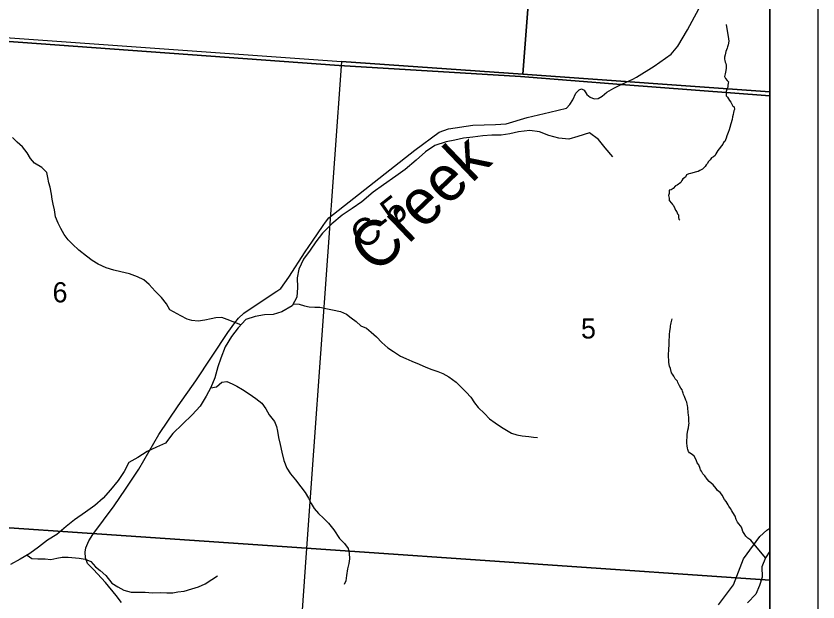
# Model space of a CAD drawing. Extents: x 0 to 34, y 0 to 22.
# Drawn here: x 7.329 to 9, y 19.223 to 20.443 of the extents above; entities that cross this region are included whole.
import ezdxf

# ---------------------------------------------------------------- set-up
doc = ezdxf.new("R2010")
doc.units = 0
for name, color, linetype in [('GM_X_Corporation', 7, 'Continuous'), ('GM_X_County_Road', 7, 'Continuous'), ('GM_X_County_Road_Text', 7, 'Continuous'), ('GM_X_Minor_River', 7, 'Continuous'), ('GM_X_Minor_River_Text', 7, 'Continuous'), ('GM_X_Section_Text', 7, 'Continuous'), ('SH_Data', 7, 'Continuous')]:
    doc.layers.add(name, color=color, linetype=linetype)

msp = doc.modelspace()

# ---------------------------------------------------------------- linework, layer by layer
at = {"layer": 'GM_X_Corporation'}
for points in [[(3.3441, 14.1), (8.9, 14.1), (8.9, 20.9), (2.1, 20.9), (2.1, 16.1353), (2.1457, 16.065), (2.3447, 15.6926), (2.4297, 15.5215), (2.465, 15.4504), (2.4884, 15.4033), (2.5769, 15.2135), (2.7849, 14.8403), (2.8931, 14.6544), (3.0297, 14.4867), (3.1386, 14.3654), (3.228, 14.2415)], [(8.9, 20.2763), (8.9, 20.9), (6.9348, 20.9), (6.9032, 20.4198), (8.0028, 20.34), (8.3805, 20.3169), (8.59, 20.3005)], [(8.4295, 20.9), (6.9414, 20.9), (6.9084, 20.4264), (8.0074, 20.3484), (8.3851, 20.3217)], [(8.9, 20.285), (8.9, 20.9), (8.4295, 20.9), (8.3851, 20.3217)], [(8.9, 16.2015), (8.9, 20.2763), (8.59, 20.3005), (8.3805, 20.3169), (8.0028, 20.34), (6.9032, 20.4198), (6.8961, 20.3303), (6.835, 19.4037), (6.824, 19.3005), (6.7876, 18.7583), (6.7629, 18.3924), (6.7536, 18.2991), (6.7043, 17.4985), (6.6962, 17.3669), (6.6852, 17.2401), (6.6249, 16.3344), (7.5782, 16.28), (7.7162, 16.2721), (7.873, 16.2628)], [(6.9084, 20.4264), (8.0074, 20.3484), (7.9347, 19.3346), (6.8376, 19.4096), (6.9011, 20.3385)], [(8.9, 19.2681), (8.9, 20.285), (8.3851, 20.3217), (8.0074, 20.3484), (7.9347, 19.3346)], [(7.9347, 19.3346), (7.864, 18.3242), (6.7676, 18.3985), (6.8303, 19.3047), (6.8376, 19.4096)], [(8.9, 18.2556), (8.9, 19.2681), (7.9347, 19.3346), (7.864, 18.3242)]]:
    msp.add_lwpolyline(points, close=True, dxfattribs=at)
at = {"layer": 'GM_X_County_Road'}
for points in [[(8.6142, 20.3116), (8.6222, 20.3154), (8.6587, 20.3383), (8.6939, 20.3635), (8.7082, 20.3797), (8.7282, 20.4138), (8.7614, 20.4759), (8.774, 20.4915)], [(7.9744, 20.0134), (7.9812, 20.0225), (8.1602, 20.1635), (8.2106, 20.2007), (8.2302, 20.2076), (8.2812, 20.2158), (8.3284, 20.2166), (8.3502, 20.2185), (8.394, 20.2311), (8.4412, 20.2427), (8.4762, 20.2506), (8.4834, 20.2588), (8.4895, 20.2685), (8.4959, 20.2823), (8.5023, 20.2893), (8.5076, 20.291), (8.513, 20.2883), (8.5187, 20.2793), (8.5257, 20.2736), (8.5338, 20.2702), (8.5418, 20.2712), (8.5505, 20.2759), (8.5602, 20.2839), (8.575, 20.2927), (8.5902, 20.3), (8.6142, 20.3116)], [(7.549, 19.2211), (7.5381, 19.2359), (7.5159, 19.2631), (7.4908, 19.2899), (7.4785, 19.3026), (7.4742, 19.3142), (7.4735, 19.3262), (7.475, 19.3351), (7.4813, 19.3499), (7.4897, 19.3633), (7.5338, 19.4229), (7.5572, 19.4574), (7.5856, 19.4991), (7.6269, 19.5712), (7.6673, 19.6308), (7.7042, 19.6828), (7.7708, 19.7836), (7.785, 19.8041), (7.7931, 19.8133), (7.8041, 19.8243), (7.8441, 19.8513), (7.8729, 19.8698), (7.8811, 19.8753), (7.8976, 19.8992), (7.9316, 19.9515), (7.9473, 19.9737), (7.9695, 20.0068), (7.9744, 20.0134)], [(8.7925, 19.2167), (8.824, 19.2581), (8.8449, 19.3126), (8.879, 19.3592), (8.8938, 19.3721), (8.9, 19.3763)]]:
    msp.add_lwpolyline(points, dxfattribs=at)
at = {"layer": 'GM_X_Minor_River'}
for points in [[(8.8087, 20.4253), (8.8133, 20.3951), (8.814, 20.3905), (8.8127, 20.3825), (8.8119, 20.3784), (8.8111, 20.3757), (8.8095, 20.3723), (8.8083, 20.3686), (8.8067, 20.3621), (8.8051, 20.3572), (8.8054, 20.3527), (8.8061, 20.35), (8.8064, 20.3469), (8.8079, 20.3439), (8.8086, 20.3404), (8.8085, 20.3332), (8.8072, 20.3257), (8.8064, 20.3222), (8.8055, 20.3166), (8.8073, 20.3127), (8.8111, 20.3085), (8.8133, 20.3058), (8.8132, 20.3028), (8.812, 20.2978), (8.812, 20.2948), (8.8104, 20.2907), (8.8091, 20.2857), (8.8087, 20.2827), (8.8086, 20.2766), (8.8116, 20.2739), (8.8134, 20.2705), (8.816, 20.2666), (8.8182, 20.2636), (8.823, 20.2547), (8.8256, 20.2539), (8.8259, 20.2479), (8.8247, 20.2452), (8.8239, 20.2418), (8.8231, 20.238), (8.8218, 20.2327), (8.821, 20.227), (8.8186, 20.218), (8.8165, 20.2108), (8.8149, 20.2055), (8.8126, 20.2002), (8.8114, 20.1968), (8.8102, 20.1934), (8.8089, 20.1885), (8.8058, 20.1817), (8.8035, 20.1791), (8.8019, 20.1761), (8.7992, 20.1723), (8.7945, 20.1663), (8.7914, 20.1626), (8.7891, 20.1592), (8.7872, 20.1558), (8.786, 20.1521), (8.7821, 20.1498), (8.7779, 20.1476), (8.7752, 20.1435), (8.7717, 20.1398), (8.7694, 20.1352), (8.7671, 20.1326), (8.7647, 20.1296), (8.7593, 20.1236), (8.754, 20.1214), (8.7505, 20.1192), (8.7467, 20.1181), (8.7346, 20.1149), (8.7311, 20.1142), (8.7262, 20.112), (8.7242, 20.1071), (8.7184, 20.1034), (8.7165, 20.1), (8.7141, 20.0959), (8.7068, 20.0903), (8.703, 20.0893), (8.6984, 20.0833), (8.6942, 20.081), (8.69, 20.08), (8.6899, 20.0731), (8.6887, 20.069), (8.6897, 20.0633), (8.69, 20.0587), (8.6952, 20.0533), (8.6967, 20.0506), (8.6993, 20.0479), (8.7018, 20.0418), (8.7029, 20.0387)], [(8.5724, 20.1498), (8.5566, 20.1681), (8.543, 20.1855), (8.5241, 20.1993), (8.4999, 20.1917), (8.481, 20.1865), (8.4605, 20.1881), (8.4393, 20.1942), (8.4197, 20.2018), (8.4, 20.2042), (8.3765, 20.2019), (8.3584, 20.1974), (8.3402, 20.1945), (8.3205, 20.1945), (8.3016, 20.1931), (8.2811, 20.1908), (8.2614, 20.1886), (8.2433, 20.1841), (8.2258, 20.1811), (8.2016, 20.1729), (8.1826, 20.16), (8.1629, 20.1426), (8.1401, 20.123), (8.1204, 20.1094), (8.0946, 20.0913), (8.0734, 20.0762), (8.0498, 20.0557), (8.0294, 20.0422), (8.0089, 20.0278), (7.9876, 20.0097), (7.9679, 19.9908), (7.9542, 19.9726), (7.942, 19.9552), (7.9284, 19.9363), (7.9185, 19.9158), (7.9154, 19.8976), (7.9161, 19.8771), (7.9145, 19.8574), (7.9046, 19.8392), (7.8834, 19.8264), (7.8652, 19.8212), (7.847, 19.8205), (7.8273, 19.8167), (7.8084, 19.8107), (7.7924, 19.7933), (7.778, 19.7751), (7.765, 19.7539), (7.7559, 19.7305), (7.7498, 19.7123), (7.7436, 19.6895), (7.7353, 19.6691), (7.7254, 19.6509), (7.7132, 19.6305), (7.6965, 19.6123), (7.676, 19.5926), (7.6562, 19.5737), (7.641, 19.5533), (7.6221, 19.545), (7.6024, 19.536), (7.5834, 19.5231), (7.5644, 19.5133), (7.5545, 19.4944), (7.5424, 19.4755), (7.5264, 19.4558), (7.5112, 19.4384), (7.4938, 19.4233), (7.474, 19.4097), (7.4513, 19.3938), (7.4338, 19.3795), (7.4141, 19.3628), (7.3951, 19.3515), (7.3762, 19.3364), (7.358, 19.3235), (7.3382, 19.3115), (7.3178, 19.3009)], [(7.798, 19.7994), (7.7817, 19.8061), (7.7693, 19.811), (7.7583, 19.8148), (7.7458, 19.814), (7.736, 19.8125), (7.7227, 19.8091), (7.7087, 19.8072), (7.6955, 19.8087), (7.6856, 19.8114), (7.6731, 19.8182), (7.65, 19.8311), (7.6429, 19.8436), (7.6323, 19.8565), (7.619, 19.8698), (7.6065, 19.8838), (7.5956, 19.8932), (7.5823, 19.8997), (7.5657, 19.9058), (7.5479, 19.9099), (7.5331, 19.9137), (7.5172, 19.9186), (7.5006, 19.9258), (7.4881, 19.9334), (7.476, 19.9429), (7.4605, 19.9554), (7.4469, 19.9675), (7.4378, 19.977), (7.4294, 19.988), (7.4226, 20.0005), (7.417, 20.0115), (7.412, 20.0247), (7.4094, 20.0395), (7.4068, 20.0509), (7.4049, 20.0611), (7.403, 20.0721), (7.4003, 20.0861), (7.3977, 20.0956), (7.3958, 20.1062), (7.3939, 20.1172), (7.3829, 20.1274), (7.3682, 20.1365), (7.3595, 20.1464), (7.3523, 20.1581), (7.3428, 20.1706), (7.3315, 20.1801), (7.3224, 20.1896)], [(8.7029, 20.0387), (8.7059, 20.0353), (8.7073, 20.0311), (8.7092, 20.0284), (8.7098, 20.023), (8.7102, 20.02), (8.712, 20.0173)], [(7.9069, 19.8436), (7.9195, 19.8428), (7.9301, 19.839), (7.9403, 19.8375), (7.9521, 19.8364), (7.9623, 19.8364), (7.9782, 19.8333), (7.9884, 19.8311), (8.0054, 19.8277), (8.0179, 19.822), (8.0278, 19.814), (8.038, 19.8064), (8.0478, 19.7977), (8.0592, 19.7924), (8.069, 19.7841), (8.0804, 19.775), (8.0917, 19.7632), (8.1042, 19.7519), (8.1155, 19.7439), (8.1303, 19.7341), (8.1416, 19.7295), (8.1541, 19.7242), (8.1693, 19.7181), (8.1833, 19.7117), (8.1958, 19.7068), (8.2083, 19.7022), (8.2188, 19.6981), (8.2313, 19.6912), (8.2461, 19.6802), (8.2571, 19.6689), (8.2673, 19.6594), (8.2771, 19.6488), (8.2847, 19.637), (8.2922, 19.6276), (8.3051, 19.6147), (8.3157, 19.6037), (8.3274, 19.5954), (8.3407, 19.5867), (8.3509, 19.5802), (8.3619, 19.5741), (8.3728, 19.5704), (8.3838, 19.5688), (8.3974, 19.5669), (8.4073, 19.5654), (8.416, 19.5647)], [(8.8906, 19.3147), (8.8605, 19.3512), (8.8541, 19.3551), (8.8497, 19.3597), (8.8464, 19.3651), (8.8438, 19.3693), (8.8423, 19.3743), (8.8409, 19.3781), (8.8387, 19.3808), (8.8353, 19.385), (8.8324, 19.3885), (8.8298, 19.3946), (8.8273, 19.4015), (8.8225, 19.4088), (8.8207, 19.4123), (8.8181, 19.4172), (8.814, 19.4223), (8.8126, 19.4249), (8.8089, 19.4318), (8.8052, 19.4361), (8.8026, 19.4411), (8.8012, 19.4445), (8.796, 19.4507), (8.7907, 19.4549), (8.7878, 19.4588), (8.7815, 19.4665), (8.7733, 19.4731), (8.7692, 19.4785), (8.7644, 19.485), (8.7599, 19.4893), (8.7573, 19.4946), (8.7555, 19.4977), (8.7544, 19.5008), (8.7515, 19.508), (8.7486, 19.5126), (8.746, 19.5184), (8.742, 19.526), (8.7379, 19.5295), (8.7323, 19.533), (8.73, 19.5361), (8.729, 19.5403), (8.7283, 19.543), (8.7272, 19.5479), (8.7266, 19.5533), (8.7267, 19.559), (8.7272, 19.5654), (8.7276, 19.5711), (8.7289, 19.5806), (8.7302, 19.5851), (8.731, 19.5912), (8.7315, 19.5946), (8.7311, 19.598), (8.7312, 19.6011), (8.7309, 19.6071), (8.7302, 19.6113), (8.7296, 19.617), (8.7296, 19.6201), (8.7289, 19.6243), (8.7286, 19.6273), (8.7279, 19.6319), (8.7276, 19.6345), (8.7266, 19.6387), (8.7247, 19.6426), (8.7222, 19.6506), (8.72, 19.6544), (8.7189, 19.6571), (8.7179, 19.6613), (8.7168, 19.664), (8.7146, 19.6678), (8.7116, 19.6724), (8.7079, 19.6793), (8.7073, 19.6827), (8.7028, 19.687), (8.6999, 19.6928), (8.6969, 19.6966), (8.6951, 19.7), (8.6926, 19.7084), (8.6904, 19.7138), (8.6894, 19.721), (8.6891, 19.7256), (8.6888, 19.7336), (8.6889, 19.7397), (8.6894, 19.7453), (8.6895, 19.751), (8.69, 19.7556), (8.6902, 19.7689), (8.6907, 19.7731), (8.6908, 19.7799), (8.6916, 19.786), (8.6921, 19.7905), (8.6925, 19.7943), (8.693, 19.7977), (8.6934, 19.8004)], [(8.6934, 19.8004), (8.6942, 19.8038), (8.6955, 19.8091), (8.6966, 19.8119)], [(7.735, 19.6687), (7.7469, 19.6708), (7.7582, 19.6803), (7.7685, 19.6814), (7.7794, 19.6769), (7.7897, 19.672), (7.8014, 19.6651), (7.815, 19.6557), (7.829, 19.6466), (7.8415, 19.6367), (7.8498, 19.625), (7.857, 19.6125), (7.8676, 19.5984), (7.8721, 19.5878), (7.874, 19.578), (7.8763, 19.5651), (7.8797, 19.5507), (7.8835, 19.5348), (7.8876, 19.517), (7.8933, 19.5014), (7.9009, 19.4893), (7.9115, 19.4768), (7.9224, 19.462), (7.9319, 19.4507), (7.9387, 19.4385), (7.944, 19.4275), (7.9504, 19.4173), (7.9595, 19.4067), (7.9697, 19.3969), (7.9807, 19.3866), (7.9913, 19.3726), (8.003, 19.3548), (8.0136, 19.3446), (8.0212, 19.3339), (8.0235, 19.3245), (8.0238, 19.3127), (8.0227, 19.3029), (8.02, 19.2915), (8.0178, 19.2775), (8.0162, 19.2665), (8.0128, 19.2589)], [(8.9, 19.3283), (8.8908, 19.3145), (8.8831, 19.2956), (8.8838, 19.2743), (8.8785, 19.2569), (8.8709, 19.2387), (8.8534, 19.2205)], [(7.3523, 19.3201), (7.3623, 19.3132), (7.3748, 19.3124), (7.3903, 19.3121), (7.402, 19.3109), (7.4141, 19.314), (7.4258, 19.3158), (7.438, 19.3158), (7.4607, 19.3136), (7.4735, 19.312), (7.4856, 19.3067), (7.4947, 19.2958), (7.5046, 19.2882), (7.5163, 19.2776), (7.5292, 19.262), (7.5416, 19.2541), (7.5538, 19.2469), (7.5693, 19.2431), (7.5984, 19.2431), (7.6135, 19.2415), (7.6302, 19.2423), (7.6434, 19.2415), (7.6563, 19.2419), (7.6665, 19.2434), (7.6794, 19.2449), (7.6957, 19.2502), (7.7093, 19.254), (7.7233, 19.2605), (7.7373, 19.2692), (7.7494, 19.2771)]]:
    msp.add_lwpolyline(points, dxfattribs=at)
at = {"layer": 'SH_Data'}
for p, q in [((9, 21), (9, 14)), ((8.9, 20.9), (8.9, 14.1))]:
    msp.add_line(p, q, dxfattribs=at)

# ---------------------------------------------------------------- texts
at = {"layer": 'GM_X_County_Road_Text'}
msp.add_text('C-5', height=0.05682, rotation=38.2345, dxfattribs=at).set_placement((8.0541, 19.9539))
at = {"layer": 'GM_X_Minor_River_Text'}
msp.add_text('Creek', height=0.09469, rotation=43.7586, dxfattribs=at).set_placement((8.0802, 19.9032))
at = {"layer": 'GM_X_Section_Text'}
for s, p in [('6', (7.4055, 19.8465)), ('5', (8.5063, 19.7712))]:
    msp.add_text(s, height=0.0419, rotation=0, dxfattribs=at).set_placement(p)

doc.saveas('drawing.dxf')
